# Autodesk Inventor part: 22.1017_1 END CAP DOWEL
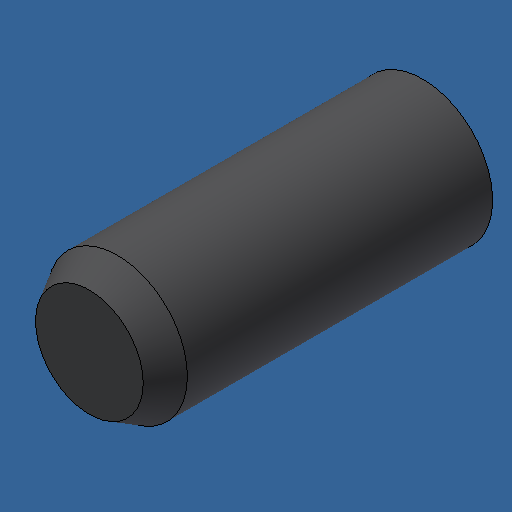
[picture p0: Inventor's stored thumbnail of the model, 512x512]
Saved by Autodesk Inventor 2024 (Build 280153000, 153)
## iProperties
Created: 2009-01
Part Number: 22.1017_1 END CAP DOWEL
Document SubType Name: Modeling
Designer: Administrator
Density: 1.06 g/cm^3
Material: ABS Plastic
Mass: 0.243239 g
Surface Area: 2.18509 cm^2
Volume: 0.229471 cm^3
Appearance: Gray
Author: Administrator
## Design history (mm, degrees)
feature "Base1"
body "Solid1"
